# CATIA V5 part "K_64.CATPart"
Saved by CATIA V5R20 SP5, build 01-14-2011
Part number: 64
Bounding box of the stored display mesh (mm): x -29.998 to 29.998, y -29.997 to 29.997, z 0 to 50
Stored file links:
  G:\Khaled_CFAO_2011\ST2M\ST2M_GR1\lpierredon\Khaled\CAD_thinkMOTION\K_64.CATPart
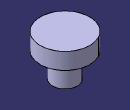
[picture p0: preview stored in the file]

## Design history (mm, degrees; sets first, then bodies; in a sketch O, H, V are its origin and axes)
Body1 (main body)
  Sketch1 on yz-plane, origin (0, 0, 0), H (0, 1, 0), V (0, 0, 1)
    line L1 (0, 40) -> (0, 50)
    point P1 (0, 40)
    line L2 (0, 50) -> (30, 50)
    line L3 (30, 50) -> (30, 30)
    line L4 (30, 30) -> (15, 30)
    line L5 (15, 30) -> (15, 0)
    point P6 (15, 0)
    line L6 (15, 0) -> (7.5, 0)
    line L7 (7.5, 0) -> (7.5, 40)
    line L8 (7.5, 40) -> (0, 40)
    distance L2 L6 = 50
    distance L4 L2 = 20
    length L4 = 15
    distance L5 L1 = 15
    length L7 = 40
    length L8 = 7.5
    coincidence: P1 V, P6 H
    vertical: L1 V, L3 V, L5 V, L7 V
    horizontal: L2 H, L4 H, L6 H, L8 H
  Shaft1: profile Sketch1, axis Sketch1.V, angle 360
